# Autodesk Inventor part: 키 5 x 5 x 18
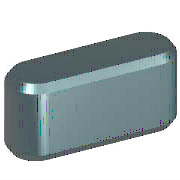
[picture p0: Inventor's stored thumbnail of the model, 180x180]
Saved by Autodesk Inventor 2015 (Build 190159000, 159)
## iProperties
Created: 2012-02
Part Number: 키 5 x 5 x 18
Material: 강철, 연강
Description: 키 및 해당 키홈
Document SubType Name: Modeling
Standard: KS B 1311
Designer: P15F
Standards Organization: KS
Language: ko-KR
Size Designation: 5 x 5 x 18
Categories: <MemberInstance><Categories><Category DisplayName="샤프트 부품" InternalName="7f7aeb1f-a693-4053-b835-cee3144e0d98" Mnemonic="SHFT"><Category DisplayName="키" Interna
Density: 1 g/cm^3
Appearance: 노란색
IsCustomPart: 1
Author: P15F
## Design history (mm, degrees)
workplane "Work Plane1"
workplane "Work Plane2"
sketch "스케치1"
  geometry: L1 (2.5, 2.5)-(15.5, 2.5); L2 (15.5, -2.5)-(2.5, -2.5); L3 (0, 9.4)-(0, -7.4) reference; L4 (-5, 0)-(30, 0) reference; L5 (18, 0)-(18, 7); A1 r 2.5 centre (2.5, 0) between (2.5, 2.5) and (2.5, -2.5); A2 r 2.5 centre (15.5, 0) between (15.5, -2.5) and (15.5, 2.5)
  constraints: 6 end point, 5 point on circle, 4 tangent, 3 point on line, 2 centre point, 1 horizontal, 1 parallel, 1 perpendicular
  dimensions: "d0" = 2.5 radius of A1 (= 0.5 x PB); "d13" = 2.5 radius of A2 (= 0.5 x PB); "d14" = 18 distance between parallel lines of L5 L3 (= NLG)
extrude "본체1" new body sketch "스케치1" taper "d3" = 0 deg; stored distance "d4" = 10
workplane "Work Plane3"
body "Solid1"
chamfer "모따기1" distance "d8" = 0.4 (= PHH); stored, may be unused: second distance "d9" = 0.4 (= PHH), angle "d15" = 45 deg
other parameters: "d1" = -3 (= -PNT), "d2" = 2 (= PH - PNT), "NLG" = 18 [user parameter; used in 3 equation terms], "PB" = 5 [user parameter; used in 2 equation terms], "PNT" = 3 [user parameter; used in 2 equation terms], "PH" = 5 [user parameter; used in 1 equation term], "PHH" = 0.4 [user parameter; used in 2 equation terms], "d10" = 0, "d16" = 0, "d17" = 0, "d18" = 0, "WDMIN" = 12 [user parameter], "PLB2" = 18 (= NLG) [user parameter], "WDMAX" = 17 [user parameter], "PLB1" = 18 (= NLG) [user parameter], "RR" = 0.16 [user parameter], "PUEB" = 2.3 [user parameter]
